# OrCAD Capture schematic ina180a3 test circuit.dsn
size A
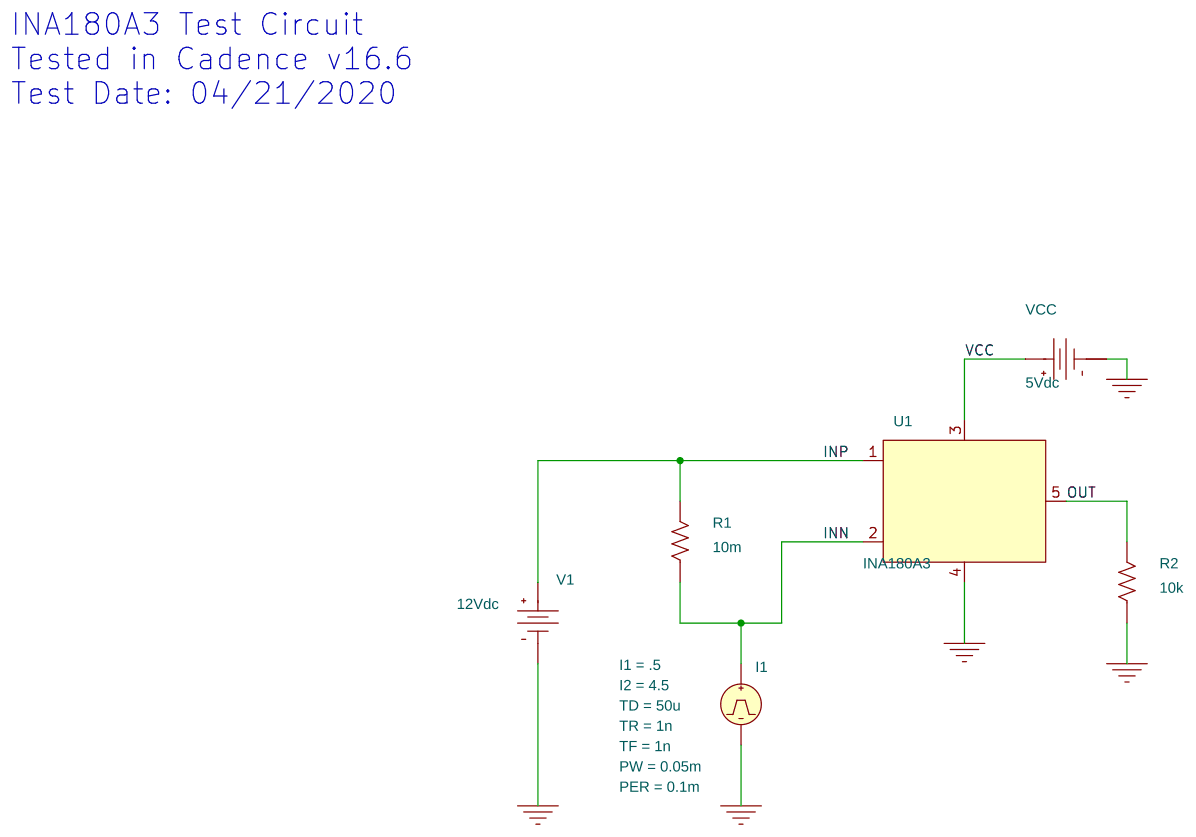
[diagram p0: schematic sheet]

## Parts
I1  IPULSE
R1  10m  [AX/RC05]
R2  10k  [AX/RC05]
U1  INA180A3
V1  VDC
VCC  VDC

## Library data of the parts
I1 = IPULSE: I1: .5; I2: 4.5; PER: 0.1m; PW: 0.05m; TD: 50u; TF: 1n; TR: 1n
R1 R2 = R
U1 = INA180A3
V1 = VDC: DC: 12Vdc
VCC = VDC: DC: 5Vdc

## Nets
VCC: U1.3(VCC) VCC.0(+)
0: I1.2(-) R2.1 U1.4(GND) V1.1(-) VCC.1(-)
INN: I1.1(+) R1.1 U1.2(INN)
INP: R1.2 U1.1(INP) V1.0(+)
OUT: R2.2 U1.5(OUT)

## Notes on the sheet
- INA180A3 Test Circuit
  Tested in Cadence v16.6
  Test Date: 04/21/2020
